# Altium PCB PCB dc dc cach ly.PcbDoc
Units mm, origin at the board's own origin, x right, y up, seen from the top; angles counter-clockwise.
Board outline 62.76 x 25.2 mm, 2 copper layers (Top Layer, Bottom Layer); 48 components, 8 nets, 120 pads, 0 vias.
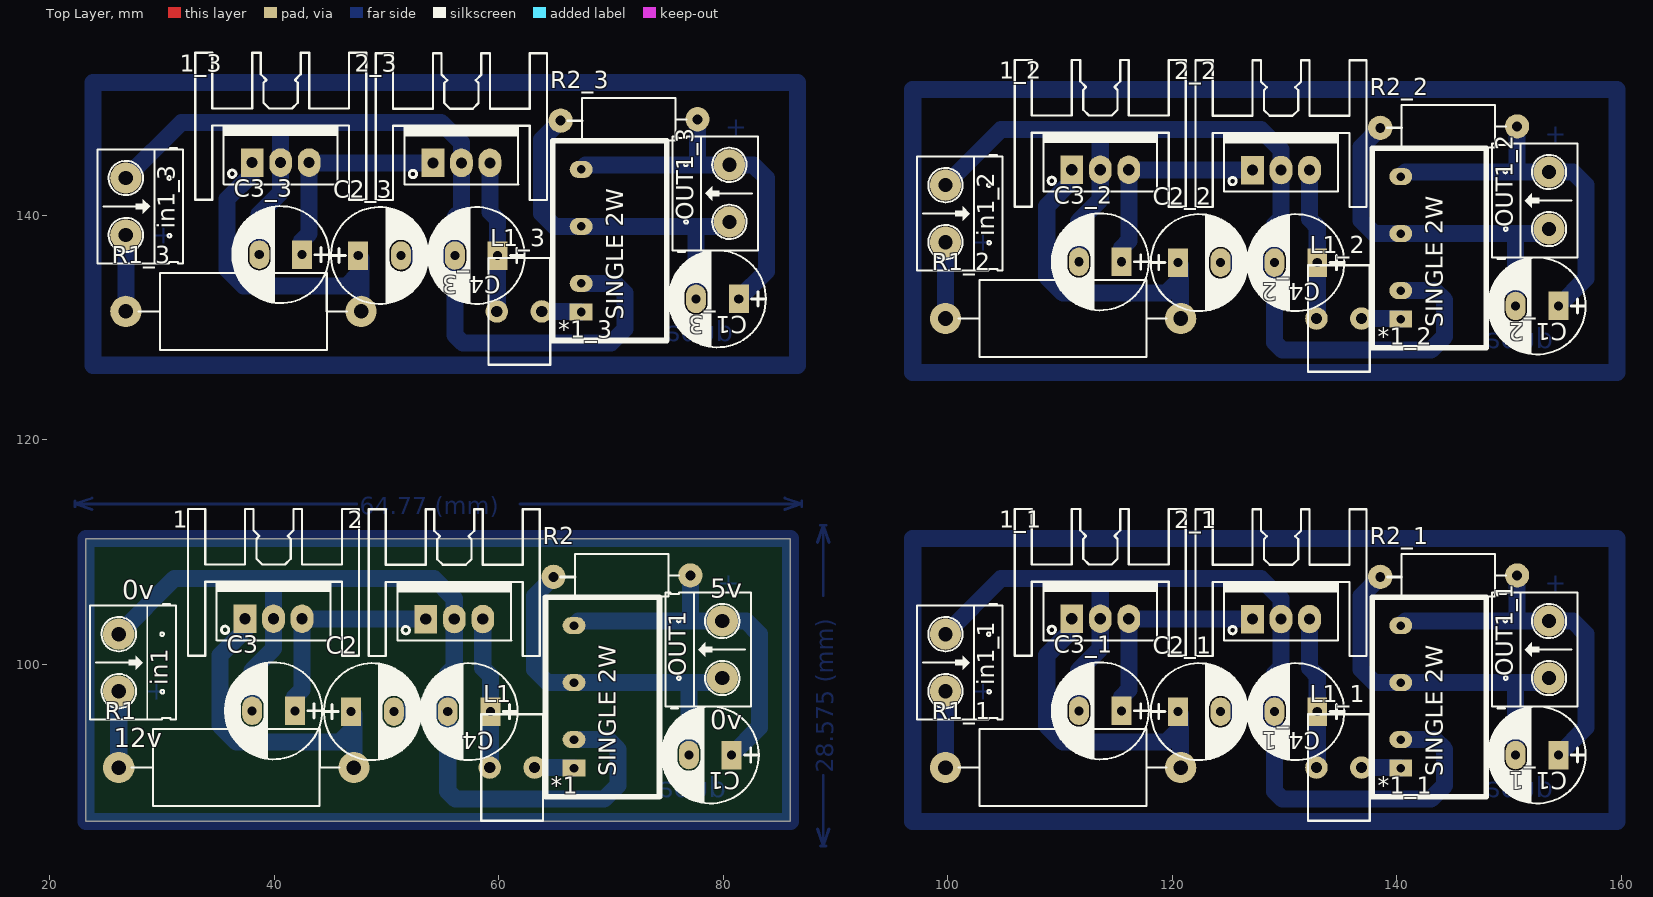
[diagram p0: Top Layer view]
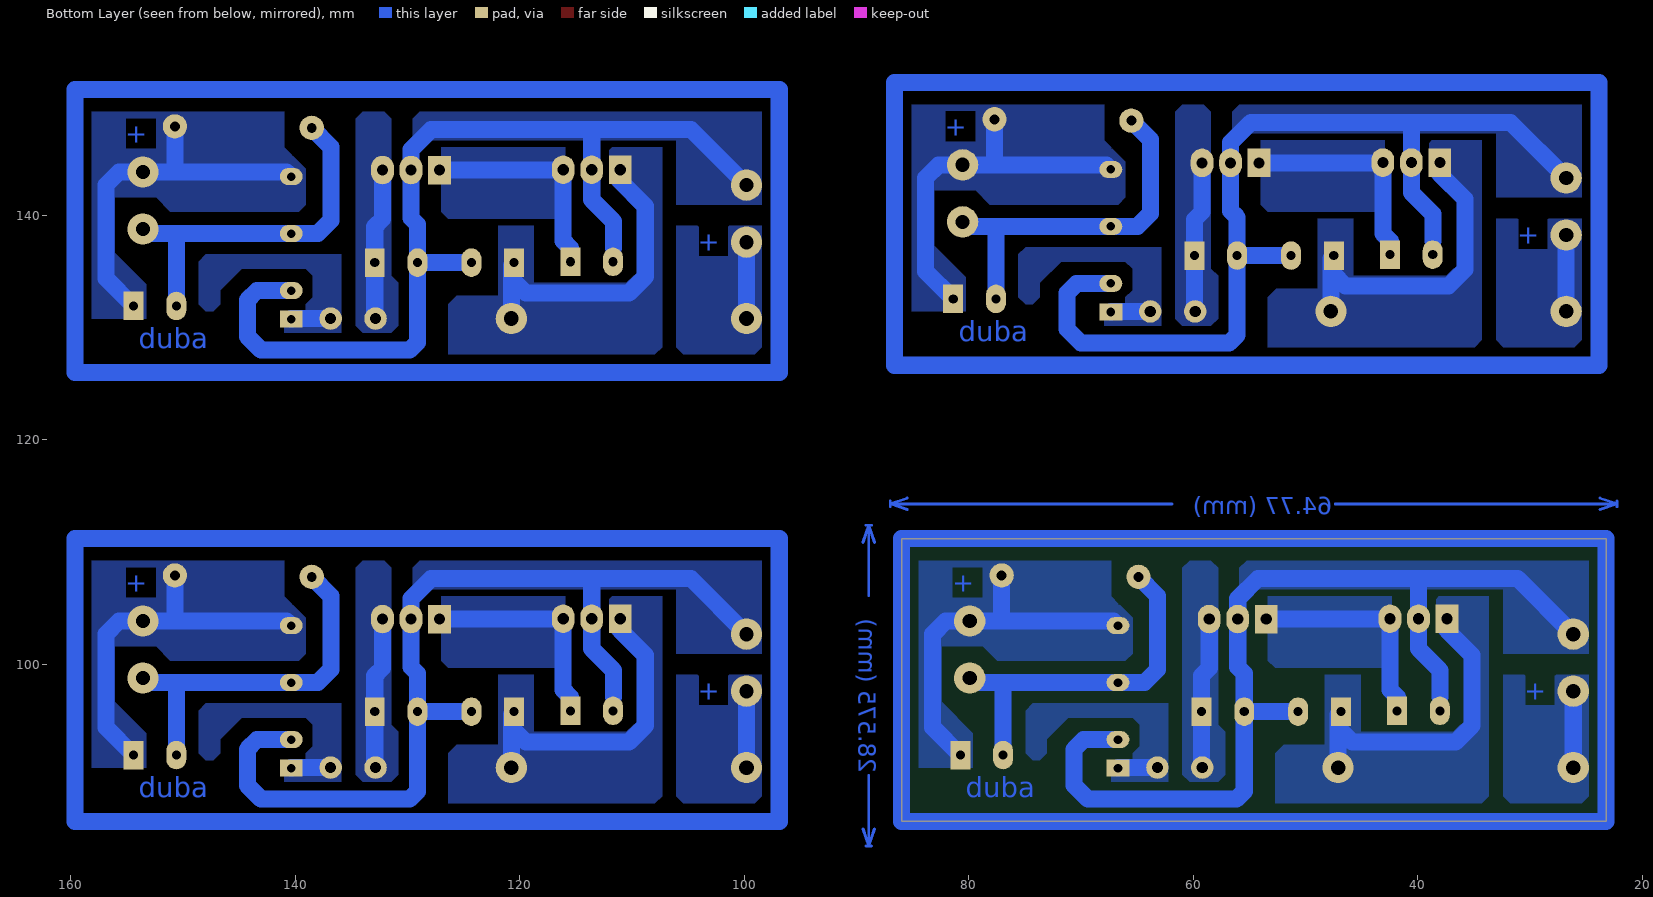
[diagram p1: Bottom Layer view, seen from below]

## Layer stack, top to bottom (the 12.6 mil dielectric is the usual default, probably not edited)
Top Solder: solder mask 0.0102, Solder Resist, Dk 3.5
Top Layer: signal copper 0.0356
Dielectric 1: dielectric 0.32, FR-4, Dk 4.8
Bottom Layer: signal copper 0.0356
Bottom Solder: solder mask 0.0102, Solder Resist, Dk 3.5

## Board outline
23.216,86.004 23.216,111.201 85.979,111.201 85.979,86.004

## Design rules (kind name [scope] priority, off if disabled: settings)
Clearance [All] p1: gap=0.254 ignorepadtopadclearanceinfootprint=FALSE except(0: Arc-Hole Track-Hole SMDPad-Hole THPad-Hole Via-Hole Fill-Hole Poly-Hole Region-Hole Text-Hole)
PolygonConnect [All] p1: connectstyle=Direct reliefconductorwidth=0.254 reliefentries=4 polygonreliefangle="90 Angle" airgapwidth=0.254
RoomDefinition "NGUON CAHC LY" [InComponentClass('NGUON CAHC LY')] p1: confinementstyle=ConfineIn formatcopy=TRUE lockcomponents=FALSE outline 178.943,27.051 208.534,27.051 208.534,48.133 178.943,48.133
RoutingVias [All] p1: holewidth=0.711 width=1.27 viastyle="Through Hole" minholewidth=0.711 minwidth=1.27 maxholewidth=0.711 maxwidth=1.27
SolderMaskExpansion [All] p1: expansion=0.102
Width [All] p1: maxlimit=2.286 minlimit=0.762 preferedwidth=1.524
30 further rules are at their usual default settings.

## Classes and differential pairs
component class "NGUON CAHC LY": 1 2 *1 C1 C2 C3 C4 in1 L1 OUT1 R1 R2

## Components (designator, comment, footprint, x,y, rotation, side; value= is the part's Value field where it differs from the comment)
1 "LM78xx" TO220H1 39.929,104.064 r0 top
1_1 "LM78xx" TO220H1 113.589,104.064 r0 top (schematic designator 1)
1_2 "LM78xx" TO220H1 113.589,144.069 r0 top (schematic designator 1)
1_3 "LM78xx" TO220H1 40.564,144.704 r0 top (schematic designator 1)
2 "LM78xx" TO220H1 56.032,104.038 r0 top
2_1 "LM78xx" TO220H1 129.692,104.038 r0 top (schematic designator 2)
2_2 "LM78xx" TO220H1 129.692,144.043 r0 top (schematic designator 2)
2_3 "LM78xx" TO220H1 56.667,144.678 r0 top (schematic designator 2)
*1 "Component_1" PCBComponent_1 66.7,90.754 r90 top
*1_1 "Component_1" PCBComponent_1 140.36,90.754 r90 top (schematic designator *1)
*1_2 "Component_1" PCBComponent_1 140.36,130.759 r90 top (schematic designator *1)
*1_3 "Component_1" PCBComponent_1 67.335,131.394 r90 top (schematic designator *1)
C1 "100uF" CP1.5/3.4 80.747,91.923 r180 top value=100uF/35V/50V
C1_1 "100uF" CP1.5/3.4 154.407,91.923 r180 top value=100uF/35V/50V (schematic designator C1)
C1_2 "100uF" CP1.5/3.4 154.407,131.928 r180 top value=100uF/35V/50V (schematic designator C1)
C1_3 "100uF" CP1.5/3.4 81.382,132.563 r180 top value=100uF/35V/50V (schematic designator C1)
C2 "100uF" CP1.5/3.4 46.838,95.783 r0 top value=100uF/35V/50V
C2_1 "100uF" CP1.5/3.4 120.498,95.783 r0 top value=100uF/35V/50V (schematic designator C2)
C2_2 "100uF" CP1.5/3.4 120.498,135.788 r0 top value=100uF/35V/50V (schematic designator C2)
C2_3 "100uF" CP1.5/3.4 47.473,136.423 r0 top value=100uF/35V/50V (schematic designator C2)
C3 "100uF" CP1.5/3.4 41.834,95.86 r180 top value=100uF/35V/50V
C3_1 "100uF" CP1.5/3.4 115.494,95.86 r180 top value=100uF/35V/50V (schematic designator C3)
C3_2 "100uF" CP1.5/3.4 115.494,135.865 r180 top value=100uF/35V/50V (schematic designator C3)
C3_3 "100uF" CP1.5/3.4 42.469,136.5 r180 top value=100uF/35V/50V (schematic designator C3)
C4 "100uF" CP1.5/3.4 59.258,95.783 r180 top value=100uF/35V/50V
C4_1 "100uF" CP1.5/3.4 132.918,95.783 r180 top value=100uF/35V/50V (schematic designator C4)
C4_2 "100uF" CP1.5/3.4 132.918,135.788 r180 top value=100uF/35V/50V (schematic designator C4)
C4_3 "100uF" CP1.5/3.4 59.893,136.423 r180 top value=100uF/35V/50V (schematic designator C4)
in1 "12v dc" HED2 26.137,102.692 r270 top value="Header 2"
in1_1 "12v dc" HED2 99.797,102.692 r270 top value="Header 2" (schematic designator in1)
in1_2 "12v dc" HED2 99.797,142.697 r270 top value="Header 2" (schematic designator in1)
in1_3 "12v dc" HED2 26.772,143.332 r270 top value="Header 2" (schematic designator in1)
L1 "L-DIP-1" L-DIP-M-9.5x5.5 61.189,90.805 r0 top value="150 mH"
L1_1 "L-DIP-1" L-DIP-M-9.5x5.5 134.849,90.805 r0 top value="150 mH" (schematic designator L1)
L1_2 "L-DIP-1" L-DIP-M-9.5x5.5 134.849,130.81 r0 top value="150 mH" (schematic designator L1)
L1_3 "L-DIP-1" L-DIP-M-9.5x5.5 61.824,131.445 r0 top value="150 mH" (schematic designator L1)
OUT1 "12v dc" HED2 79.908,98.781 r90 top value="Header 2"
OUT1_1 "12v dc" HED2 153.568,98.781 r90 top value="Header 2" (schematic designator OUT1)
OUT1_2 "12v dc" HED2 153.568,138.786 r90 top value="Header 2" (schematic designator OUT1)
OUT1_3 "12v dc" HED2 80.543,139.421 r90 top value="Header 2" (schematic designator OUT1)
R1 "Res" RES-2W 36.805,90.932 r180 top
R1_1 "Res" RES-2W 110.465,90.932 r180 top (schematic designator R1)
R1_2 "Res" RES-2W 110.465,130.937 r180 top (schematic designator R1)
R1_3 "Res" RES-2W 37.44,131.572 r180 top (schematic designator R1)
R2 "2.4 MOhm" RES-1/2W 70.46,107.925 r0 top
R2_1 "2.4 MOhm" RES-1/2W 144.12,107.925 r0 top (schematic designator R2)
R2_2 "2.4 MOhm" RES-1/2W 144.12,147.93 r0 top (schematic designator R2)
R2_3 "2.4 MOhm" RES-1/2W 71.095,148.565 r0 top (schematic designator R2)

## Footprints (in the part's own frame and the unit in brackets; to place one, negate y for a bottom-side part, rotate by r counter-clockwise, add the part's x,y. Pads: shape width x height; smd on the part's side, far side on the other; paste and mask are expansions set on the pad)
CP1.5/3.4 [mil] "Tu hoa 220->470uF,16V, 470uF/16V,25V"
  rect 70x100 hole 32: 1(0,0)
  oval 70x100 hole 32: 2(150,0)
  silkscreen extent -95,-170 245,170, body extent -85,-157 230,157, height 446
HED2 [mil] "Header 2, 2 pin, hight 300mil, Pin to Pin 200, Colour Green"
  round 110 hole 50: 1(0,0) 2(200,0)
  silkscreen extent -106,-100 300,200, body extent -92,-140 302,155, height 394
L-DIP-M-9.5x5.5 [mm] "Body 9.5x5.5mm, 2 leads"
  round 2 hole 1: 1(-2,0) 2(2,0)
  silkscreen extent -2.75,-4.75 2.75,4.75, body extent -2.57,-5.05 2.57,5.05, height 10.07
PCBComponent_1 [mil]
  rect 60x80 hole 30: 1(0,0)
  oval 60x80 hole 30: 2(100,0) 3(300,0) 4(500,0)
  silkscreen extent -100,-300 600,100
RES-1/2W [mil]
  round 85 hole 35: 1(-220,-5) 2(260,0)
  silkscreen extent -195,-74 221,75, body extent -230,-60 270,56, height 121
RES-2W [mil] "R2W, 2 pin, 700mil"
  round 110 hole 51.18: 1(-405,5) 2(420,5)
  silkscreen extent -355,-130 375,140, body extent -428,-126 446,134, height 277
TO220H1 [mil] "TO-220 - 1-2-3"
  round 0 all layers, no hole: 0(0,230)
  rect 80x100 hole 39: 1(-100,0)
  oval 80x100 hole 39: 2(0,0) 3(100,0)
  silkscreen extent -300,-130 300,385, body extent -246,-82 250,329, height 1000

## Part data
1 1_1 1_2 1_3 2 2_1 2_2 2_3: "Positive Voltage Regulator"
C1 C1_1 C1_2 C1_3 C2 C2_1 C2_2 C2_3 C3 C3_1 C3_2 C3_3 C4 C4_1 C4_2 C4_3: library part CP3, "Cap 100uF/35V - 470uF/16V"
in1 in1_1 in1_2 in1_3 OUT1 OUT1_1 OUT1_2 OUT1_3: library part Hed2, "Header 2 (Green)"
L1 L1_1 L1_2 L1_3: "Inductor"
R1 R1_1 R1_2 R1_3: Manufacturer="Generic Components"
R2 R2_1 R2_2 R2_3: library part Res, "Res", Manufacturer="Generic Components"

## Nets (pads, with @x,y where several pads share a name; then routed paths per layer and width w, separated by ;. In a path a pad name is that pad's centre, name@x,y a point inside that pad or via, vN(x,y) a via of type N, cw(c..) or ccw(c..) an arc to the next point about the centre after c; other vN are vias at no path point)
Net1_1: 1.1 C2.1 R1.1 | length 28.3
  Bottom Layer w1.524: 1.1 37.389,103.048 35.154,100.813 35.154,94.539 36.627,93.066 45.796,93.066 46.838,94.107 ; C2.1 47.092,95.529 R1.1
Net1_3: 1.3 2.1 C3.1 | length 18.3
  Bottom Layer w1.524: C3.1@41.808,97.079 42.469,97.739 1.3 42.494,104.038 2.1
Net2_3: 2.3 C4.1 L1.1 | length 13.5
  Bottom Layer w1.524: 2.3 58.572,99.67 59.258,98.984 C4.1 59.258,90.875 L1.1
Net*1_1: *1.1 L1.2 | length 3.5
  Bottom Layer w1.524: L1.2 66.65,90.805 *1.1
Net*1_2: 1.2 2.2 *1.2 C2.2 C3.2 C4.2 in1.1 | length 89.8
  Bottom Layer w1.524: in1.1 31.09,107.645 40.157,107.645 ; C3.2@37.998,97.079 37.998,99.466 39.929,101.397 1.2 39.929,107.417 40.157,107.645 ; C2.2 C4.2 ; *1.2 69.748,93.294 70.612,92.431 70.612,89.23 69.367,87.986 56.159,87.986 55.448,88.697 C4.2 ; 40.157,107.645 54.229,107.645 56.032,105.842 2.2 56.032,99.771 55.448,99.187 C4.2
Net*1_3: *1.3 C1.2 OUT1.1 R2.1 | length 32.8
  Bottom Layer w1.524: R2.1 63.17,106.096 63.17,99.543 64.338,98.374 *1.3 76.911,98.374 ; C1.2 76.937,98.349 76.911,98.374 ; OUT1.1 79.502,98.374 76.911,98.374
Net*1_4: *1.4 C1.1 OUT1.2 R2.2 | length 33
  Bottom Layer w1.524: *1.4 67.107,103.861 77.013,103.861 ; R2.2 77.064,103.911 77.013,103.861 ; C1.1 83.21,94.386 83.21,102.692 82.042,103.861 OUT1.2 77.013,103.861
Netin1_2: in1.2 R1.2 | length 6.8
  Bottom Layer w1.524: R1.2 in1.2
pads on no net: 1.0 1_1.0 1_1.1 1_1.2 1_1.3 1_2.0 1_2.1 1_2.2 1_2.3 1_3.0 1_3.1 1_3.2 1_3.3 2.0 2_1.0 2_1.1 2_1.2 2_1.3 2_2.0 2_2.1 2_2.2 2_2.3 2_3.0 2_3.1 2_3.2 2_3.3 *1_1.1 *1_1.2 *1_1.3 *1_1.4 *1_2.1 *1_2.2 *1_2.3 *1_2.4 *1_3.1 *1_3.2 *1_3.3 *1_3.4 C1_1.1 C1_1.2 C1_2.1 C1_2.2 C1_3.1 C1_3.2 C2_1.1 C2_1.2 C2_2.1 C2_2.2 C2_3.1 C2_3.2 C3_1.1 C3_1.2 C3_2.1 C3_2.2 C3_3.1 C3_3.2 C4_1.1 C4_1.2 C4_2.1 C4_2.2 C4_3.1 C4_3.2 in1_1.1 in1_1.2 in1_2.1 in1_2.2 in1_3.1 in1_3.2 L1_1.1 L1_1.2 L1_2.1 L1_2.2 L1_3.1 L1_3.2 OUT1_1.1 OUT1_1.2 OUT1_2.1 OUT1_2.2 OUT1_3.1 OUT1_3.2 R1_1.1 R1_1.2 R1_2.1 R1_2.2 R1_3.1 R1_3.2 R2_1.1 R2_1.2 R2_2.1 R2_2.2 R2_3.1 R2_3.2
copper on no net: | length 1459.6
  Bottom Layer w0.254: 22.225,114.046 22.225,114.554 ; 23.749,113.792 22.225,114.3 ; 23.749,114.808 22.225,114.3 ; 47.348,114.3 22.225,114.3 ; 61.872,114.3 86.995,114.3 ; 85.471,113.792 86.995,114.3 ; 85.471,114.808 86.995,114.3 ; 86.995,114.046 86.995,114.554 ; 88.392,85.344 88.9,83.82 ; 88.392,110.871 88.9,112.395 ; 88.646,83.82 89.154,83.82 ; 88.646,112.395 89.154,112.395 ; 88.9,90.084 88.9,83.82 ; 88.9,106.131 88.9,112.395 ; 89.408,85.344 88.9,83.82 ; 89.408,110.871 88.9,112.395
  Bottom Layer w1.524: 26.772,131.445 26.772,138.252 ; 26.772,143.332 31.725,148.285 40.792,148.285 ; 38.024,144.704 38.024,143.688 35.789,141.453 35.789,135.179 37.262,133.706 46.431,133.706 47.473,134.747 ; 38.633,137.719 38.633,140.106 40.564,142.037 40.564,144.704 40.564,148.057 40.792,148.285 ; 42.443,137.719 43.104,138.379 43.104,144.704 43.129,144.678 54.127,144.678 ; 47.473,136.423 47.727,136.169 47.727,131.445 ; 51.283,136.423 56.083,136.423 ; 59.207,144.678 59.207,140.31 59.893,139.624 59.893,136.423 59.893,131.515 59.824,131.445 ; 63.824,131.445 67.285,131.445 67.335,131.394 ; 65.507,148.438 63.805,146.736 63.805,140.183 64.973,139.014 67.335,139.014 77.546,139.014 ; 67.335,133.934 70.383,133.934 71.247,133.071 71.247,129.87 70.002,128.626 56.794,128.626 56.083,129.337 56.083,136.423 ; 67.335,144.094 67.742,144.501 77.648,144.501 ; 77.572,132.563 77.572,138.989 77.546,139.014 ; 77.699,148.565 77.699,144.551 77.648,144.501 ; 80.543,139.421 80.137,139.014 77.546,139.014 ; 81.382,132.563 83.845,135.026 83.845,143.332 82.677,144.501 80.543,144.501 77.648,144.501 ; 99.797,90.805 99.797,97.612 ; 99.797,102.692 104.75,107.645 113.817,107.645 ; 99.797,130.81 99.797,137.617 ; 99.797,142.697 104.75,147.65 113.817,147.65 ; 111.049,104.064 111.049,103.048 108.814,100.813 108.814,94.539 110.287,93.066 119.456,93.066 120.498,94.107 ; 111.049,144.069 111.049,143.053 108.814,140.818 108.814,134.544 110.287,133.071 119.456,133.071 120.498,134.112 ; 111.658,97.079 111.658,99.466 113.589,101.397 113.589,104.064 113.589,107.417 113.817,107.645 ; 111.658,137.084 111.658,139.471 113.589,141.402 113.589,144.069 113.589,147.422 113.817,147.65 ; 115.468,97.079 116.129,97.739 116.129,104.064 116.154,104.038 127.152,104.038 ; 115.468,137.084 116.129,137.744 116.129,144.069 116.154,144.043 127.152,144.043 ; 120.498,95.783 120.752,95.529 120.752,90.805 ; 120.498,135.788 120.752,135.534 120.752,130.81 ; 124.308,95.783 129.108,95.783 ; 124.308,135.788 129.108,135.788 ; 132.232,104.038 132.232,99.67 132.918,98.984 132.918,95.783 132.918,90.875 132.849,90.805 ; 132.232,144.043 132.232,139.675 132.918,138.989 132.918,135.788 132.918,130.88 132.849,130.81 ; 136.849,90.805 140.31,90.805 140.36,90.754 ; 136.849,130.81 140.31,130.81 140.36,130.759 ; 138.532,107.798 136.83,106.096 136.83,99.543 137.998,98.374 140.36,98.374 150.571,98.374 ; 138.532,147.803 136.83,146.101 136.83,139.548 137.998,138.379 140.36,138.379 150.571,138.379 ; 140.36,93.294 143.408,93.294 144.272,92.431 144.272,89.23 143.027,87.986 129.819,87.986 129.108,88.697 129.108,95.783 ; 140.36,103.454 140.767,103.861 150.673,103.861 ; 140.36,133.299 143.408,133.299 144.272,132.436 144.272,129.235 143.027,127.991 129.819,127.991 129.108,128.702 129.108,135.788 ; 140.36,143.459 140.767,143.866 150.673,143.866 ; 150.597,91.923 150.597,98.349 150.571,98.374 ; 150.597,131.928 150.597,138.354 150.571,138.379 ; 150.724,107.925 150.724,103.911 150.673,103.861 ; 150.724,147.93 150.724,143.916 150.673,143.866 ; 153.568,98.781 153.162,98.374 150.571,98.374 ; 153.568,138.786 153.162,138.379 150.571,138.379 ; 154.407,91.923 156.87,94.386 156.87,102.692 155.702,103.861 153.568,103.861 150.673,103.861 ; 154.407,131.928 156.87,134.391 156.87,142.697 155.702,143.866 153.568,143.866 150.673,143.866 ; 40.792,148.285 54.864,148.285 56.667,146.482 56.667,144.678 56.667,140.411 56.083,139.827 56.083,136.423 ; 113.817,107.645 127.889,107.645 129.692,105.842 129.692,104.038 129.692,99.771 129.108,99.187 129.108,95.783 ; 113.817,147.65 127.889,147.65 129.692,145.847 129.692,144.043 129.692,139.776 129.108,139.192 129.108,135.788 ; 23.216,86.004 85.979,86.004 85.979,111.201 23.216,111.201 23.216,86.004 ; 23.851,126.644 23.851,151.841 86.614,151.841 86.614,126.644 23.851,126.644 ; 96.876,86.004 96.876,111.201 159.639,111.201 159.639,86.004 96.876,86.004 ; 96.876,126.009 96.876,151.206 159.639,151.206 159.639,126.009 96.876,126.009

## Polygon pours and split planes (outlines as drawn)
no net on Bottom Layer "Bottom Layer-No Net" (solid, pour order 96): 25.4,139.7 33.02,139.7 33.02,128.905 25.4,128.905
no net on Bottom Layer "Bottom Layer-No Net" (solid, pour order 94): 45.72,139.7 48.895,139.7 48.895,133.477 52.578,133.477 53.34,132.715 53.34,128.27 34.925,128.27 34.29,128.905 34.29,135.255 36.83,135.255 37.465,134.62 45.72,134.62
no net on Bottom Layer "Bottom Layer-No Net" (solid, pour order 92): 34.29,135.255 34.29,146.685 38.735,146.685 38.989,146.431 38.989,143.637 36.449,141.097 36.449,135.255
no net on Bottom Layer "Bottom Layer-No Net" (solid, pour order 90): 53.975,146.685 53.975,140.97 53.34,140.335 43.053,140.335 42.926,140.462 42.926,146.685
no net on Bottom Layer "Bottom Layer-No Net" (solid, pour order 88): 67.945,149.86 67.945,146.685 67.31,146.05 67.31,140.97 78.105,140.97 79.375,142.24 83.058,142.24 83.058,137.287 80.264,134.493 80.264,131.445 85.09,131.445 85.09,149.86
no net on Bottom Layer "Bottom Layer-No Net" (solid, pour order 86): 62.865,137.16 62.865,130.175 67.945,130.175 67.945,132.08 66.04,132.08 66.04,132.715 65.405,133.35 65.405,135.255 66.04,135.89 71.755,135.89 73.66,133.985 73.66,132.715 74.295,132.08 74.93,132.08 75.565,132.715 75.565,136.525 74.93,137.16
no net on Bottom Layer "Bottom Layer-No Net" (solid, pour order 84): 25.4,141.605 33.02,141.605 33.02,147.32 56.515,147.32 56.515,149.225 55.88,149.86 25.4,149.86
no net on Bottom Layer "Bottom Layer-No Net" (solid, pour order 82): 59.055,149.86 58.42,149.225 58.42,135.255 57.785,134.62 57.785,130.81 58.42,130.175 60.96,130.175 61.595,130.81 61.595,149.225 60.96,149.86
no net on Bottom Layer "Bottom Layer-No Net" (solid, pour order 80): 25.4,128.905 26.035,128.27 32.385,128.27 33.02,128.905 33.02,130.175 25.4,130.175
no net on Bottom Layer "Bottom Layer-No Net" (solid, pour order 78): 67.31,146.05 66.04,144.78 66.04,141.605 66.675,140.97 67.31,140.97
no net on Bottom Layer "Bottom Layer-No Net" (solid, pour order 76): 98.425,139.065 106.045,139.065 106.045,128.27 98.425,128.27
no net on Bottom Layer "Bottom Layer-No Net" (solid, pour order 74): 118.745,139.065 121.92,139.065 121.92,132.842 125.603,132.842 126.365,132.08 126.365,127.635 107.95,127.635 107.315,128.27 107.315,134.62 109.855,134.62 110.49,133.985 118.745,133.985
no net on Bottom Layer "Bottom Layer-No Net" (solid, pour order 72): 107.315,134.62 107.315,146.05 111.76,146.05 112.014,145.796 112.014,143.002 109.474,140.462 109.474,134.62
no net on Bottom Layer "Bottom Layer-No Net" (solid, pour order 70): 127,146.05 127,140.335 126.365,139.7 116.078,139.7 115.951,139.827 115.951,146.05
no net on Bottom Layer "Bottom Layer-No Net" (solid, pour order 68): 140.97,149.225 140.97,146.05 140.335,145.415 140.335,140.335 151.13,140.335 152.4,141.605 156.083,141.605 156.083,136.652 153.289,133.858 153.289,130.81 158.115,130.81 158.115,149.225
no net on Bottom Layer "Bottom Layer-No Net" (solid, pour order 66): 135.89,136.525 135.89,129.54 140.97,129.54 140.97,131.445 139.065,131.445 139.065,132.08 138.43,132.715 138.43,134.62 139.065,135.255 144.78,135.255 146.685,133.35 146.685,132.08 147.32,131.445 147.955,131.445 148.59,132.08 148.59,135.89 147.955,136.525
no net on Bottom Layer "Bottom Layer-No Net" (solid, pour order 64): 98.425,140.97 106.045,140.97 106.045,146.685 129.54,146.685 129.54,148.59 128.905,149.225 98.425,149.225
no net on Bottom Layer "Bottom Layer-No Net" (solid, pour order 62): 132.08,149.225 131.445,148.59 131.445,134.62 130.81,133.985 130.81,130.175 131.445,129.54 133.985,129.54 134.62,130.175 134.62,148.59 133.985,149.225
no net on Bottom Layer "Bottom Layer-No Net" (solid, pour order 60): 98.425,128.27 99.06,127.635 105.41,127.635 106.045,128.27 106.045,129.54 98.425,129.54
no net on Bottom Layer "Bottom Layer-No Net" (solid, pour order 58): 140.335,145.415 139.065,144.145 139.065,140.97 139.7,140.335 140.335,140.335
no net on Bottom Layer "Bottom Layer-No Net" (solid, pour order 56): 98.425,99.06 106.045,99.06 106.045,88.265 98.425,88.265
no net on Bottom Layer "Bottom Layer-No Net" (solid, pour order 54): 118.745,99.06 121.92,99.06 121.92,92.837 125.603,92.837 126.365,92.075 126.365,87.63 107.95,87.63 107.315,88.265 107.315,94.615 109.855,94.615 110.49,93.98 118.745,93.98
no net on Bottom Layer "Bottom Layer-No Net" (solid, pour order 52): 107.315,94.615 107.315,106.045 111.76,106.045 112.014,105.791 112.014,102.997 109.474,100.457 109.474,94.615
no net on Bottom Layer "Bottom Layer-No Net" (solid, pour order 50): 127,106.045 127,100.33 126.365,99.695 116.078,99.695 115.951,99.822 115.951,106.045
no net on Bottom Layer "Bottom Layer-No Net" (solid, pour order 48): 140.97,109.22 140.97,106.045 140.335,105.41 140.335,100.33 151.13,100.33 152.4,101.6 156.083,101.6 156.083,96.647 153.289,93.853 153.289,90.805 158.115,90.805 158.115,109.22
no net on Bottom Layer "Bottom Layer-No Net" (solid, pour order 46): 135.89,96.52 135.89,89.535 140.97,89.535 140.97,91.44 139.065,91.44 139.065,92.075 138.43,92.71 138.43,94.615 139.065,95.25 144.78,95.25 146.685,93.345 146.685,92.075 147.32,91.44 147.955,91.44 148.59,92.075 148.59,95.885 147.955,96.52
no net on Bottom Layer "Bottom Layer-No Net" (solid, pour order 44): 98.425,100.965 106.045,100.965 106.045,106.68 129.54,106.68 129.54,108.585 128.905,109.22 98.425,109.22
no net on Bottom Layer "Bottom Layer-No Net" (solid, pour order 42): 132.08,109.22 131.445,108.585 131.445,94.615 130.81,93.98 130.81,90.17 131.445,89.535 133.985,89.535 134.62,90.17 134.62,108.585 133.985,109.22
no net on Bottom Layer "Bottom Layer-No Net" (solid, pour order 40): 98.425,88.265 99.06,87.63 105.41,87.63 106.045,88.265 106.045,89.535 98.425,89.535
no net on Bottom Layer "Bottom Layer-No Net" (solid, pour order 38): 140.335,105.41 139.065,104.14 139.065,100.965 139.7,100.33 140.335,100.33
Net*1_4 on Bottom Layer "Bottom Layer-No Net" (solid, pour order 36): 66.675,105.41 65.405,104.14 65.405,100.965 66.04,100.33 66.675,100.33
Netin1_2 on Bottom Layer "Bottom Layer-No Net" (solid, pour order 34): 24.765,88.265 25.4,87.63 31.75,87.63 32.385,88.265 32.385,89.535 24.765,89.535
Net2_3 on Bottom Layer "Bottom Layer-No Net" (solid, pour order 32): 58.42,109.22 57.785,108.585 57.785,94.615 57.15,93.98 57.15,90.17 57.785,89.535 60.325,89.535 60.96,90.17 60.96,108.585 60.325,109.22
Net*1_2 on Bottom Layer "Bottom Layer-No Net" (solid, pour order 28): 24.765,100.965 32.385,100.965 32.385,106.68 55.88,106.68 55.88,108.585 55.245,109.22 24.765,109.22
Net*1_1 on Bottom Layer "Bottom Layer-No Net" (solid, pour order 24): 62.23,96.52 62.23,89.535 67.31,89.535 67.31,91.44 65.405,91.44 65.405,92.075 64.77,92.71 64.77,94.615 65.405,95.25 71.12,95.25 73.025,93.345 73.025,92.075 73.66,91.44 74.295,91.44 74.93,92.075 74.93,95.885 74.295,96.52
Net*1_4 on Bottom Layer "Bottom Layer-No Net" (solid, pour order 18): 67.31,109.22 67.31,106.045 66.675,105.41 66.675,100.33 77.47,100.33 78.74,101.6 82.423,101.6 82.423,96.647 79.629,93.853 79.629,90.805 84.455,90.805 84.455,109.22
Net1_3 on Bottom Layer "Bottom Layer-No Net" (solid, pour order 10): 53.34,106.045 53.34,100.33 52.705,99.695 42.418,99.695 42.291,99.822 42.291,106.045
Net1_1 on Bottom Layer "Bottom Layer-No Net" (solid, pour order 8): 33.655,94.615 33.655,106.045 38.1,106.045 38.354,105.791 38.354,102.997 35.814,100.457 35.814,94.615
Net1_1 on Bottom Layer "Bottom Layer-No Net" (solid, pour order 6): 45.085,99.06 48.26,99.06 48.26,92.837 51.943,92.837 52.705,92.075 52.705,87.63 34.29,87.63 33.655,88.265 33.655,94.615 36.195,94.615 36.83,93.98 45.085,93.98
Netin1_2 on Bottom Layer "Bottom Layer-No Net" (solid, pour order 4): 24.765,99.06 32.385,99.06 32.385,88.265 24.765,88.265

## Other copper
Bottom Layer:
  text "+" at 80.162,147.091 h1.7
  text "+" at 153.187,146.456 h1.7
  text "+" at 29.159,137.465 h1.7
  text "+" at 102.184,136.83 h1.7
  text "duba" at 80.899,128.778 h1.78
  text "duba" at 153.924,128.143 h1.78
  text "64.77 (mm)" at 47.602,113.386 h1.52
  text "+" at 79.527,106.451 h1.7
  text "+" at 153.187,106.451 h1.7
  text "+" at 28.524,96.825 h1.7
  text "+" at 102.184,96.825 h1.7
  text "28.575 (mm)" at 89.814,90.338 h1.52 r90
  text "duba" at 80.264,88.138 h1.78
  text "duba" at 153.924,88.138 h1.78

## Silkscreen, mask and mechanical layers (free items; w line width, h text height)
Top Overlay:
  text "5v" at 78.842,105.918 h1.7
  text "0v" at 26.467,105.791 h1.7
  text "0v" at 78.842,94.234 h1.7
  text "12v" at 25.705,92.634 h1.7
